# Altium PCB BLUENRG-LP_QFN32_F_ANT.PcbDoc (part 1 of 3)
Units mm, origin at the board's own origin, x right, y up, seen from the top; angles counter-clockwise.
Board outline 90.84 x 54.03 mm, 4 copper layers (Top Layer, G1 Layer, G2 Layer, Bottom Layer), stack 1.697 mm thick; 142 components, 101 nets, 450 pads, 662 vias.
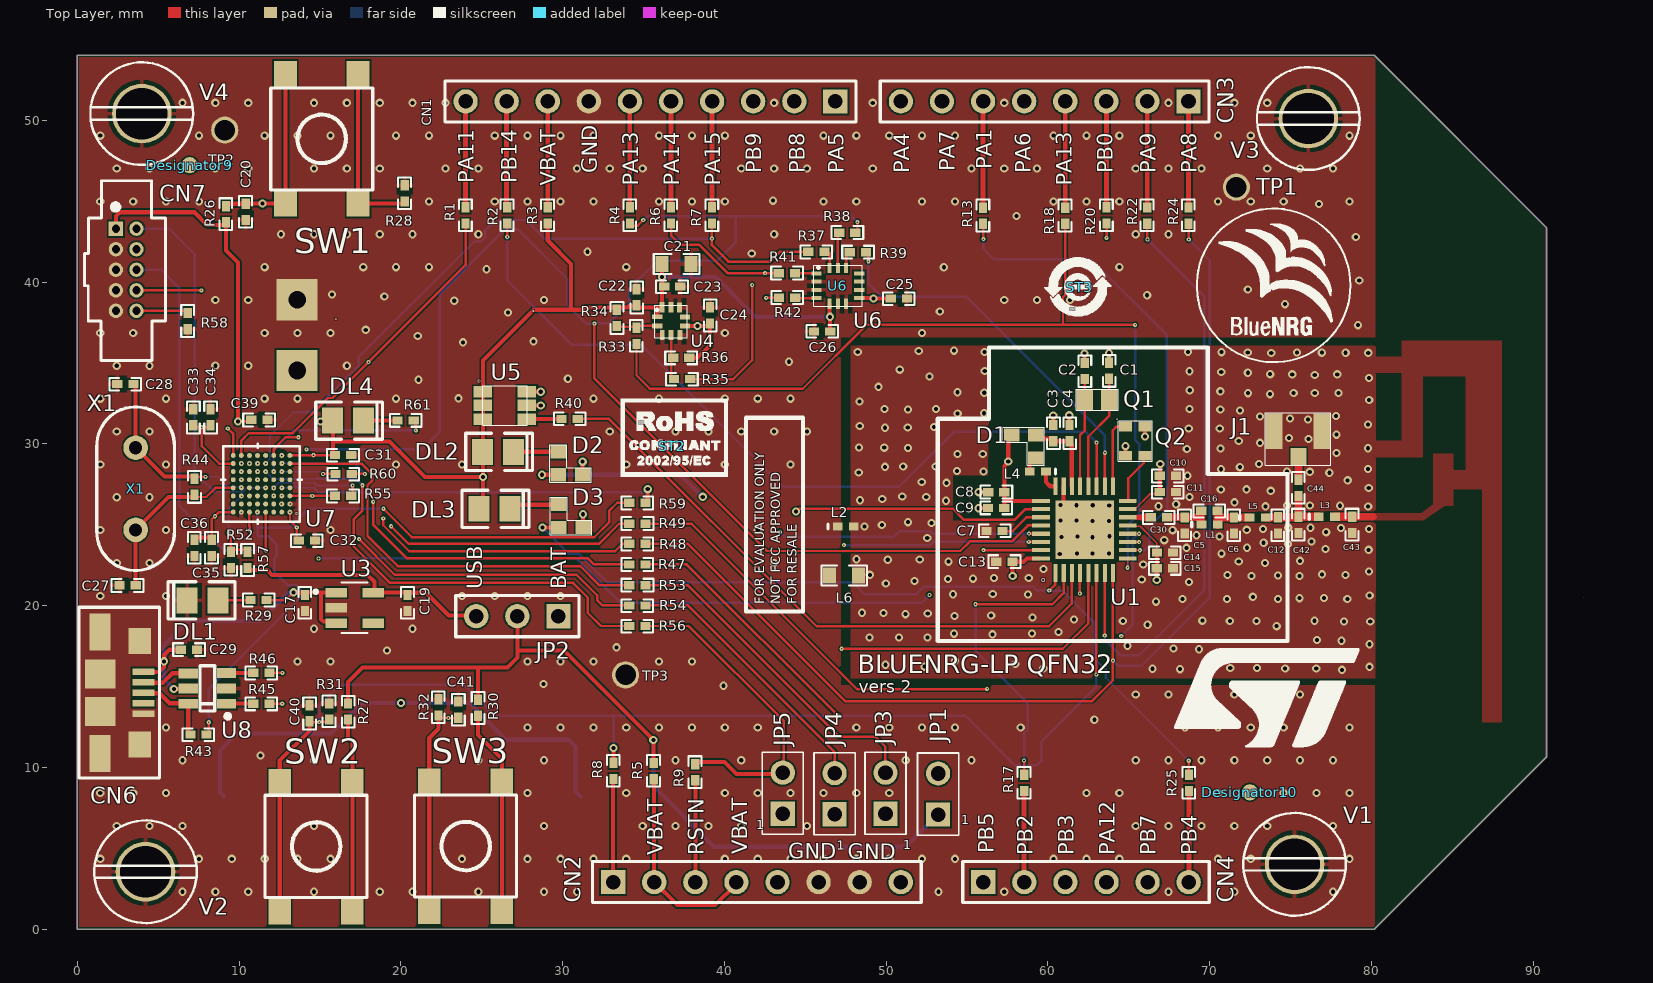
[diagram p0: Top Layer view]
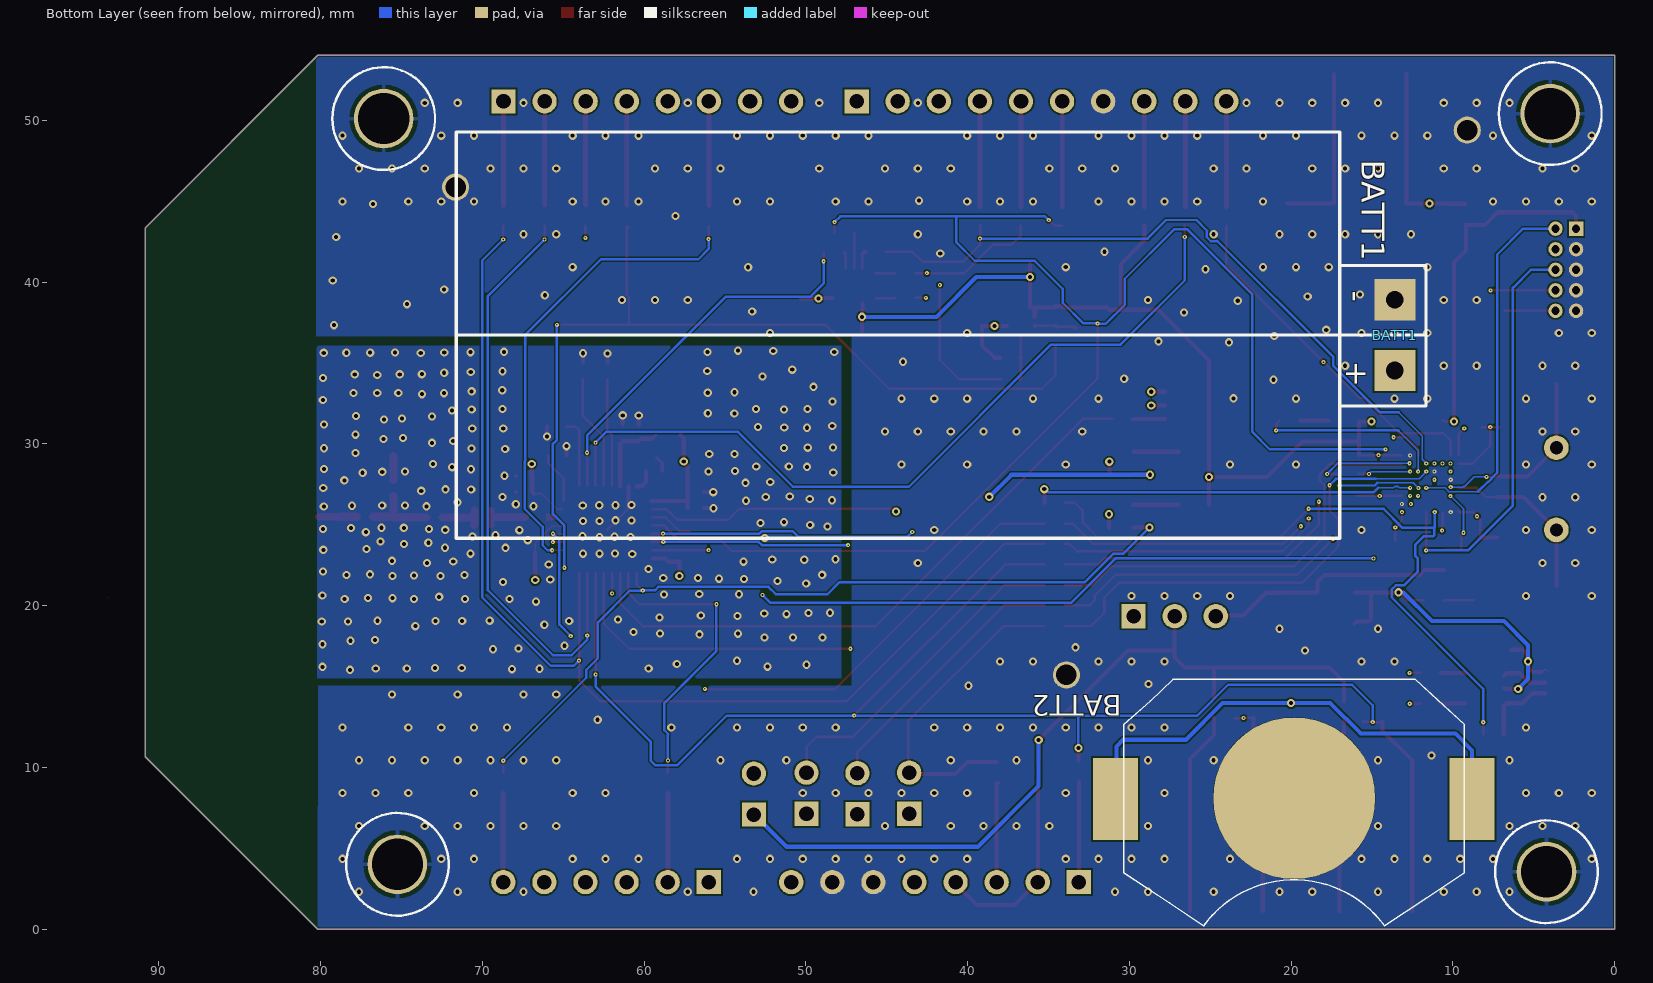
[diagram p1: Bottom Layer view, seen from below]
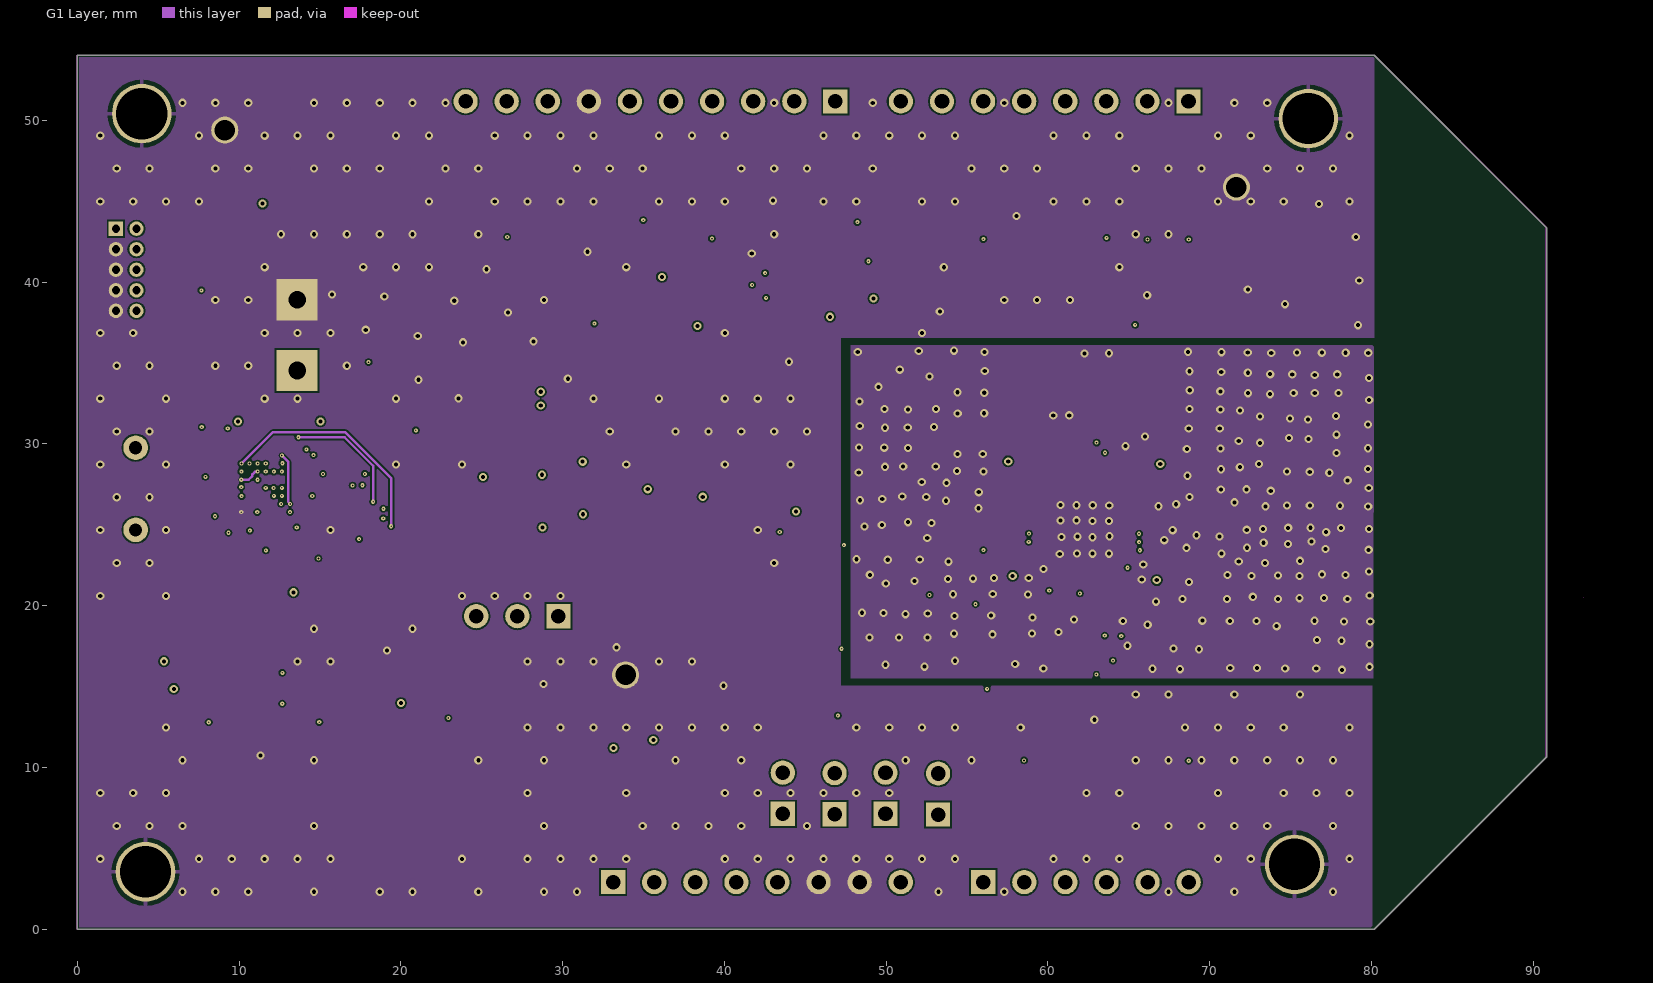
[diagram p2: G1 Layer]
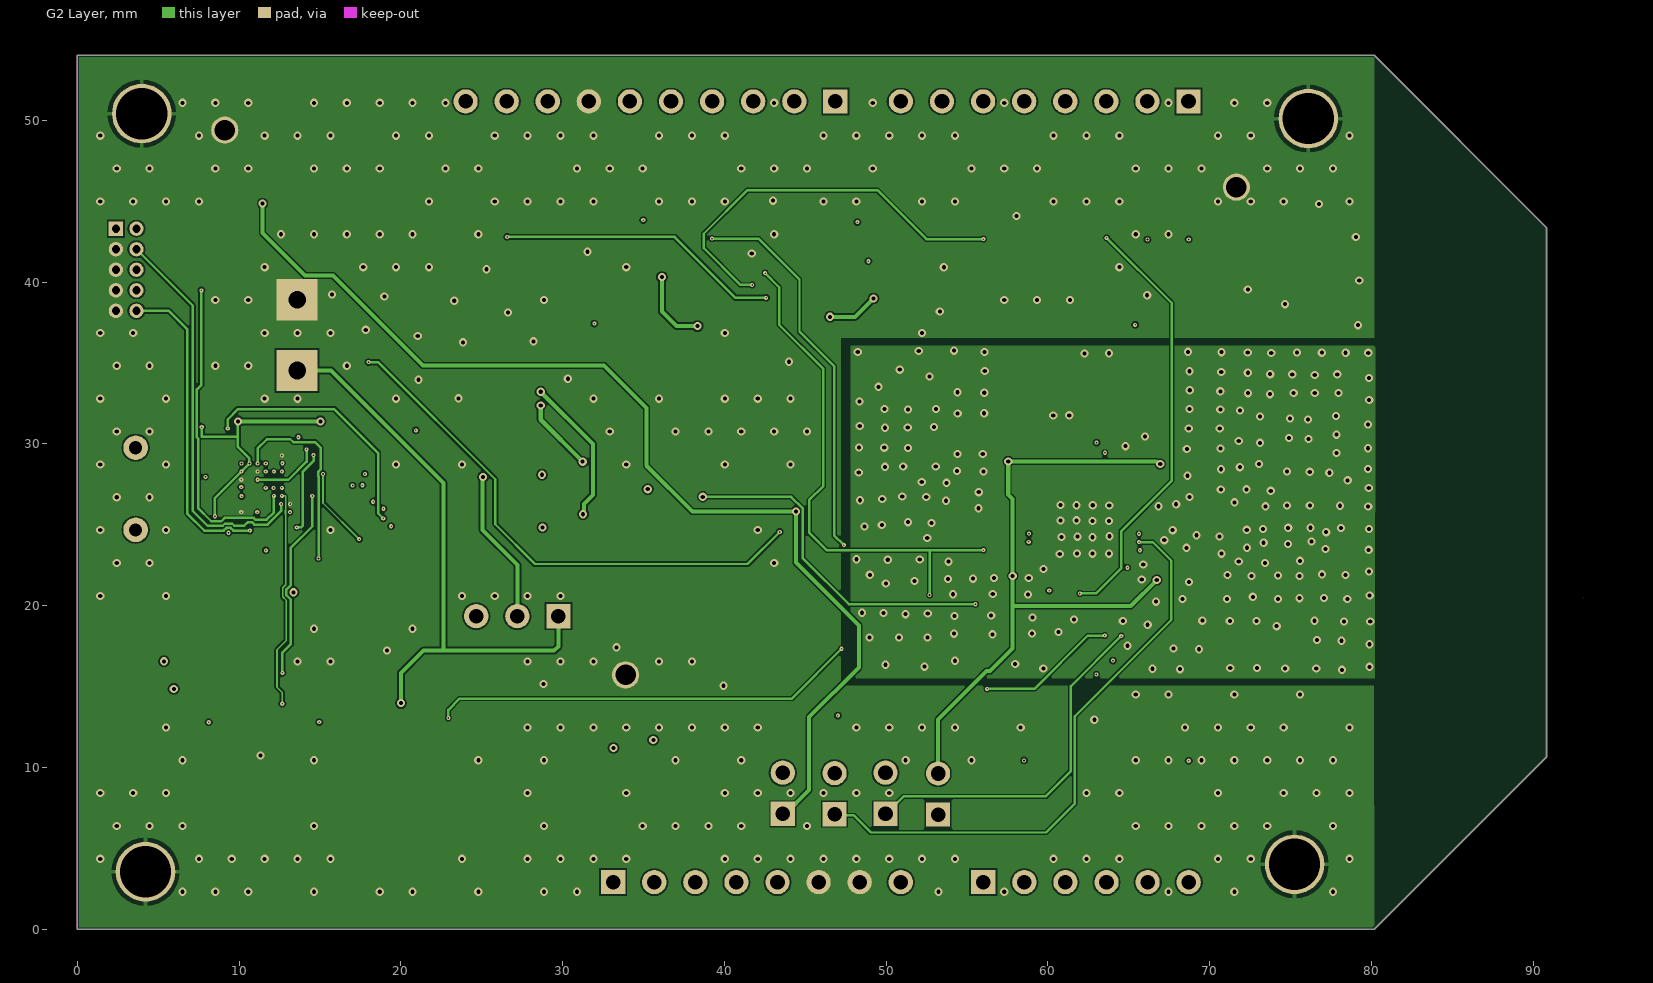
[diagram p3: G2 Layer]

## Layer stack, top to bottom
Top Solder: solder mask 0.0102, Solder Resist, Dk 3.5
Top Layer: signal copper 0.0356
Dielectric 1: dielectric 0.2997, FR-4, Dk 4.3
G1 Layer: signal copper 0.0178
Dielectric2: dielectric 0.9906, FR-4, Dk 4.3
G2 Layer: signal copper 0.0178
Dielectric3: dielectric 0.2997, FR-4, Dk 4.3
Bottom Layer: signal copper 0.0356
Bottom Solder: solder mask 0.0102, Solder Resist, Dk 3.5

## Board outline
0,0 80.169,0 90.838,10.669 90.838,43.357 80.169,54.026 0,54.026
cut-out: 93.094,20.529

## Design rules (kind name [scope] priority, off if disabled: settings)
Clearance Clearance_2 [InNamedPolygon('NONET_TOP_LAYER_P040')] p1: gap=0 ignorepadtopadclearanceinfootprint=FALSE
Clearance Clearance_1 [InNamedPolygon('NONET_TOP_LAYER_P040') vs InNet('GND_RF')] p2: gap=0.254 ignorepadtopadclearanceinfootprint=FALSE except(0: Arc-Hole Track-Hole SMDPad-Hole THPad-Hole Via-Hole Fill-Hole Poly-Hole Region-Hole Text-Hole)
Clearance "Stitching GND_1" [IsStitchingVia and InNet('GND') vs (IsVia and (Not IsStitchingVia)) Or IsPad] p3: gap=0.102 ignorepadtopadclearanceinfootprint=FALSE except(0: SMDPad-Via)
Clearance "Stitching GND" [IsStitchingVia and InNet('GND_RF') vs (IsVia and (Not IsStitchingVia)) Or IsPad] p4: gap=0.102 ignorepadtopadclearanceinfootprint=FALSE
Clearance [All] p5: gap=0.102 ignorepadtopadclearanceinfootprint=FALSE
ComponentClearance [All] p1: gap=0.127 collisioncheckmode=3 verticalgap=0.127 showdistances=FALSE
HoleSize [All] p1: absolutevalues=TRUE maxlimit=5.08 minlimit=0.025 maxpercent=80.000 minpercent=20.000
HoleToHoleClearance [All] p1: gap=0.127 allowstackedmicrovias=TRUE
MinimumSolderMaskSliver [All] p1: minsoldermaskwidth=0
PlaneConnect [All] p1: planeconnectstyle=Relief reliefexpansion=2.54 reliefentries=4 reliefconductorwidth=2.54 reliefairgap=2.54
PolygonConnect [All] p1: connectstyle=Relief reliefconductorwidth=0.254 reliefentries=4 polygonreliefangle="90 Angle" airgapwidth=0.254
RoutingLayers RoutingLayers_1 [All] p1: top layer_v5=TRUE mid layer 1_v5=TRUE mid layer 2_v5=TRUE bottom layer_v5=TRUE
RoutingLayers [All] p2: top layer_v5=TRUE mid layer 1_v5=TRUE mid layer 2_v5=TRUE bottom layer_v5=TRUE
RoutingVias [All] p1: holewidth=0.711 width=1.27 viastyle="Through Hole" minholewidth=0 minwidth=0.254 maxholewidth=0.254 maxwidth=0.508
ShortCircuit [InNamedPolygon('NONET_TOP_LAYER_P040') vs InNamedPolygon('Top Layer-GND_RF')] p1: allowed=TRUE
SilkToSilkClearance [All] p1: silktosilkclearance=0
SilkToSolderMaskClearance [IsPad] p1: minsilkscreentomaskgap=0 clearancetoexposedcopper=TRUE
SolderMaskExpansion [All] p1: expansion=0
ViasUnderSMD VIA_UnderSMD_471 [(Name = 'X1-2')] p1: allowed=TRUE
ViasUnderSMD VIA_UnderSMD_470 [(Name = 'X1-1')] p2: allowed=FALSE
ViasUnderSMD VIA_UnderSMD_469 [(Name = 'V4-1')] p3: allowed=FALSE
ViasUnderSMD VIA_UnderSMD_468 [(Name = 'V3-1')] p4: allowed=FALSE
ViasUnderSMD VIA_UnderSMD_467 [(Name = 'V2-1')] p5: allowed=FALSE
ViasUnderSMD VIA_UnderSMD_466 [(Name = 'V1-1')] p6: allowed=FALSE
ViasUnderSMD VIA_UnderSMD_465 [(Name = 'U9-8')] p7: allowed=FALSE
ViasUnderSMD VIA_UnderSMD_464 [(Name = 'U9-7')] p8: allowed=FALSE
ViasUnderSMD VIA_UnderSMD_463 [(Name = 'U9-6')] p9: allowed=FALSE
ViasUnderSMD VIA_UnderSMD_462 [(Name = 'U9-5')] p10: allowed=FALSE
ViasUnderSMD VIA_UnderSMD_461 [(Name = 'U9-4')] p11: allowed=FALSE
ViasUnderSMD VIA_UnderSMD_460 [(Name = 'U9-3')] p12: allowed=FALSE
ViasUnderSMD VIA_UnderSMD_459 [(Name = 'U9-2')] p13: allowed=FALSE
ViasUnderSMD VIA_UnderSMD_458 [(Name = 'U9-1')] p14: allowed=FALSE
ViasUnderSMD VIA_UnderSMD_457 [(Name = 'U8-6')] p15: allowed=FALSE
ViasUnderSMD VIA_UnderSMD_456 [(Name = 'U8-5')] p16: allowed=FALSE
ViasUnderSMD VIA_UnderSMD_455 [(Name = 'U8-4')] p17: allowed=FALSE
ViasUnderSMD VIA_UnderSMD_454 [(Name = 'U8-3')] p18: allowed=FALSE
ViasUnderSMD VIA_UnderSMD_453 [(Name = 'U8-2')] p19: allowed=FALSE
ViasUnderSMD VIA_UnderSMD_452 [(Name = 'U8-1')] p20: allowed=FALSE
ViasUnderSMD VIA_UnderSMD_451 [(Name = 'U7-48')] p21: allowed=FALSE
ViasUnderSMD VIA_UnderSMD_450 [(Name = 'U7-47')] p22: allowed=FALSE
ViasUnderSMD VIA_UnderSMD_449 [(Name = 'U7-46')] p23: allowed=FALSE
ViasUnderSMD VIA_UnderSMD_448 [(Name = 'U7-45')] p24: allowed=FALSE
ViasUnderSMD VIA_UnderSMD_447 [(Name = 'U7-44')] p25: allowed=FALSE
ViasUnderSMD VIA_UnderSMD_446 [(Name = 'U7-43')] p26: allowed=FALSE
ViasUnderSMD VIA_UnderSMD_445 [(Name = 'U7-42')] p27: allowed=FALSE
ViasUnderSMD VIA_UnderSMD_444 [(Name = 'U7-41')] p28: allowed=FALSE
ViasUnderSMD VIA_UnderSMD_443 [(Name = 'U7-40')] p29: allowed=FALSE
ViasUnderSMD VIA_UnderSMD_442 [(Name = 'U7-39')] p30: allowed=FALSE
ViasUnderSMD VIA_UnderSMD_441 [(Name = 'U7-38')] p31: allowed=FALSE
ViasUnderSMD VIA_UnderSMD_440 [(Name = 'U7-37')] p32: allowed=FALSE
ViasUnderSMD VIA_UnderSMD_439 [(Name = 'U7-36')] p33: allowed=FALSE
ViasUnderSMD VIA_UnderSMD_438 [(Name = 'U7-35')] p34: allowed=FALSE
ViasUnderSMD VIA_UnderSMD_437 [(Name = 'U7-34')] p35: allowed=FALSE
ViasUnderSMD VIA_UnderSMD_436 [(Name = 'U7-33')] p36: allowed=FALSE
ViasUnderSMD VIA_UnderSMD_435 [(Name = 'U7-32')] p37: allowed=FALSE
ViasUnderSMD VIA_UnderSMD_434 [(Name = 'U7-31')] p38: allowed=FALSE
ViasUnderSMD VIA_UnderSMD_433 [(Name = 'U7-30')] p39: allowed=FALSE
ViasUnderSMD VIA_UnderSMD_432 [(Name = 'U7-29')] p40: allowed=FALSE
ViasUnderSMD VIA_UnderSMD_431 [(Name = 'U7-49')] p41: allowed=FALSE
ViasUnderSMD VIA_UnderSMD_430 [(Name = 'U7-28')] p42: allowed=FALSE
ViasUnderSMD VIA_UnderSMD_429 [(Name = 'U7-27')] p43: allowed=FALSE
ViasUnderSMD VIA_UnderSMD_428 [(Name = 'U7-26')] p44: allowed=FALSE
ViasUnderSMD VIA_UnderSMD_427 [(Name = 'U7-25')] p45: allowed=FALSE
ViasUnderSMD VIA_UnderSMD_426 [(Name = 'U7-24')] p46: allowed=FALSE
ViasUnderSMD VIA_UnderSMD_425 [(Name = 'U7-23')] p47: allowed=FALSE
ViasUnderSMD VIA_UnderSMD_424 [(Name = 'U7-22')] p48: allowed=FALSE
ViasUnderSMD VIA_UnderSMD_423 [(Name = 'U7-21')] p49: allowed=FALSE
ViasUnderSMD VIA_UnderSMD_422 [(Name = 'U7-20')] p50: allowed=FALSE
ViasUnderSMD VIA_UnderSMD_421 [(Name = 'U7-19')] p51: allowed=FALSE
ViasUnderSMD VIA_UnderSMD_420 [(Name = 'U7-18')] p52: allowed=FALSE
ViasUnderSMD VIA_UnderSMD_419 [(Name = 'U7-17')] p53: allowed=FALSE
ViasUnderSMD VIA_UnderSMD_418 [(Name = 'U7-16')] p54: allowed=FALSE
ViasUnderSMD VIA_UnderSMD_417 [(Name = 'U7-15')] p55: allowed=FALSE
ViasUnderSMD VIA_UnderSMD_416 [(Name = 'U7-14')] p56: allowed=FALSE
ViasUnderSMD VIA_UnderSMD_415 [(Name = 'U7-13')] p57: allowed=FALSE
ViasUnderSMD VIA_UnderSMD_414 [(Name = 'U7-12')] p58: allowed=FALSE
ViasUnderSMD VIA_UnderSMD_413 [(Name = 'U7-11')] p59: allowed=FALSE
ViasUnderSMD VIA_UnderSMD_412 [(Name = 'U7-10')] p60: allowed=FALSE
ViasUnderSMD VIA_UnderSMD_411 [(Name = 'U7-9')] p61: allowed=FALSE
ViasUnderSMD VIA_UnderSMD_410 [(Name = 'U7-8')] p62: allowed=FALSE
ViasUnderSMD VIA_UnderSMD_409 [(Name = 'U7-7')] p63: allowed=FALSE
ViasUnderSMD VIA_UnderSMD_408 [(Name = 'U7-6')] p64: allowed=FALSE
ViasUnderSMD VIA_UnderSMD_407 [(Name = 'U7-5')] p65: allowed=FALSE
ViasUnderSMD VIA_UnderSMD_406 [(Name = 'U7-4')] p66: allowed=FALSE
ViasUnderSMD VIA_UnderSMD_405 [(Name = 'U7-3')] p67: allowed=FALSE
ViasUnderSMD VIA_UnderSMD_404 [(Name = 'U7-2')] p68: allowed=FALSE
ViasUnderSMD VIA_UnderSMD_403 [(Name = 'U7-1')] p69: allowed=FALSE
ViasUnderSMD VIA_UnderSMD_402 [(Name = 'U6-14')] p70: allowed=FALSE
ViasUnderSMD VIA_UnderSMD_401 [(Name = 'U6-13')] p71: allowed=FALSE
ViasUnderSMD VIA_UnderSMD_400 [(Name = 'U6-12')] p72: allowed=FALSE
ViasUnderSMD VIA_UnderSMD_399 [(Name = 'U6-11')] p73: allowed=FALSE
ViasUnderSMD VIA_UnderSMD_398 [(Name = 'U6-10')] p74: allowed=FALSE
ViasUnderSMD VIA_UnderSMD_397 [(Name = 'U6-9')] p75: allowed=FALSE
ViasUnderSMD VIA_UnderSMD_396 [(Name = 'U6-8')] p76: allowed=FALSE
ViasUnderSMD VIA_UnderSMD_395 [(Name = 'U6-7')] p77: allowed=FALSE
ViasUnderSMD VIA_UnderSMD_394 [(Name = 'U6-6')] p78: allowed=FALSE
ViasUnderSMD VIA_UnderSMD_393 [(Name = 'U6-5')] p79: allowed=FALSE
ViasUnderSMD VIA_UnderSMD_392 [(Name = 'U6-4')] p80: allowed=FALSE
ViasUnderSMD VIA_UnderSMD_391 [(Name = 'U6-3')] p81: allowed=FALSE
ViasUnderSMD VIA_UnderSMD_390 [(Name = 'U6-2')] p82: allowed=FALSE
ViasUnderSMD VIA_UnderSMD_389 [(Name = 'U6-1')] p83: allowed=FALSE
ViasUnderSMD VIA_UnderSMD_388 [(Name = 'U5-6')] p84: allowed=FALSE
ViasUnderSMD VIA_UnderSMD_387 [(Name = 'U5-5')] p85: allowed=FALSE
ViasUnderSMD VIA_UnderSMD_386 [(Name = 'U5-4')] p86: allowed=FALSE
ViasUnderSMD VIA_UnderSMD_385 [(Name = 'U5-3')] p87: allowed=FALSE
ViasUnderSMD VIA_UnderSMD_384 [(Name = 'U5-2')] p88: allowed=FALSE
ViasUnderSMD VIA_UnderSMD_383 [(Name = 'U5-1')] p89: allowed=FALSE
ViasUnderSMD VIA_UnderSMD_382 [(Name = 'U4-10')] p90: allowed=FALSE
ViasUnderSMD VIA_UnderSMD_381 [(Name = 'U4-9')] p91: allowed=FALSE
ViasUnderSMD VIA_UnderSMD_380 [(Name = 'U4-8')] p92: allowed=FALSE
ViasUnderSMD VIA_UnderSMD_379 [(Name = 'U4-7')] p93: allowed=FALSE
ViasUnderSMD VIA_UnderSMD_378 [(Name = 'U4-6')] p94: allowed=FALSE
ViasUnderSMD VIA_UnderSMD_377 [(Name = 'U4-5')] p95: allowed=FALSE
ViasUnderSMD VIA_UnderSMD_376 [(Name = 'U4-4')] p96: allowed=FALSE
ViasUnderSMD VIA_UnderSMD_375 [(Name = 'U4-3')] p97: allowed=FALSE
ViasUnderSMD VIA_UnderSMD_374 [(Name = 'U4-2')] p98: allowed=FALSE
ViasUnderSMD VIA_UnderSMD_373 [(Name = 'U4-1')] p99: allowed=FALSE
ViasUnderSMD VIA_UnderSMD_372 [(Name = 'U3-7')] p100: allowed=FALSE
ViasUnderSMD VIA_UnderSMD_371 [(Name = 'U3-6')] p101: allowed=FALSE
ViasUnderSMD VIA_UnderSMD_370 [(Name = 'U3-5')] p102: allowed=FALSE
ViasUnderSMD VIA_UnderSMD_369 [(Name = 'U3-1')] p103: allowed=FALSE
ViasUnderSMD VIA_UnderSMD_368 [(Name = 'U3-2')] p104: allowed=FALSE
ViasUnderSMD VIA_UnderSMD_367 [(Name = 'U3-3')] p105: allowed=FALSE
ViasUnderSMD VIA_UnderSMD_366 [(Name = 'U3-4')] p106: allowed=FALSE
ViasUnderSMD VIA_UnderSMD_365 [(Name = 'U2-3')] p107: allowed=FALSE
ViasUnderSMD VIA_UnderSMD_364 [(Name = 'U2-1')] p108: allowed=FALSE
ViasUnderSMD VIA_UnderSMD_363 [(Name = 'U2-2')] p109: allowed=FALSE
ViasUnderSMD VIA_UnderSMD_362 [(Name = 'U2-4')] p110: allowed=FALSE
ViasUnderSMD VIA_UnderSMD_361 [(Name = 'U1-48')] p111: allowed=FALSE
ViasUnderSMD VIA_UnderSMD_360 [(Name = 'U1-47')] p112: allowed=FALSE
ViasUnderSMD VIA_UnderSMD_359 [(Name = 'U1-46')] p113: allowed=FALSE
ViasUnderSMD VIA_UnderSMD_358 [(Name = 'U1-45')] p114: allowed=FALSE
ViasUnderSMD VIA_UnderSMD_357 [(Name = 'U1-44')] p115: allowed=FALSE
ViasUnderSMD VIA_UnderSMD_356 [(Name = 'U1-43')] p116: allowed=FALSE
ViasUnderSMD VIA_UnderSMD_355 [(Name = 'U1-42')] p117: allowed=FALSE
ViasUnderSMD VIA_UnderSMD_354 [(Name = 'U1-41')] p118: allowed=FALSE
ViasUnderSMD VIA_UnderSMD_353 [(Name = 'U1-40')] p119: allowed=FALSE
ViasUnderSMD VIA_UnderSMD_352 [(Name = 'U1-39')] p120: allowed=FALSE
ViasUnderSMD VIA_UnderSMD_351 [(Name = 'U1-38')] p121: allowed=FALSE
ViasUnderSMD VIA_UnderSMD_350 [(Name = 'U1-37')] p122: allowed=FALSE
ViasUnderSMD VIA_UnderSMD_349 [(Name = 'U1-36')] p123: allowed=FALSE
ViasUnderSMD VIA_UnderSMD_348 [(Name = 'U1-35')] p124: allowed=FALSE
ViasUnderSMD VIA_UnderSMD_347 [(Name = 'U1-34')] p125: allowed=FALSE
ViasUnderSMD VIA_UnderSMD_346 [(Name = 'U1-33')] p126: allowed=FALSE
ViasUnderSMD VIA_UnderSMD_345 [(Name = 'U1-32')] p127: allowed=FALSE
ViasUnderSMD VIA_UnderSMD_344 [(Name = 'U1-31')] p128: allowed=FALSE
ViasUnderSMD VIA_UnderSMD_343 [(Name = 'U1-30')] p129: allowed=FALSE
ViasUnderSMD VIA_UnderSMD_342 [(Name = 'U1-29')] p130: allowed=FALSE
ViasUnderSMD VIA_UnderSMD_341 [(Name = 'U1-49')] p131: allowed=FALSE
ViasUnderSMD VIA_UnderSMD_340 [(Name = 'U1-28')] p132: allowed=FALSE
ViasUnderSMD VIA_UnderSMD_339 [(Name = 'U1-27')] p133: allowed=FALSE
ViasUnderSMD VIA_UnderSMD_338 [(Name = 'U1-26')] p134: allowed=FALSE
ViasUnderSMD VIA_UnderSMD_337 [(Name = 'U1-25')] p135: allowed=FALSE
ViasUnderSMD VIA_UnderSMD_336 [(Name = 'U1-24')] p136: allowed=FALSE
ViasUnderSMD VIA_UnderSMD_335 [(Name = 'U1-23')] p137: allowed=FALSE
ViasUnderSMD VIA_UnderSMD_334 [(Name = 'U1-22')] p138: allowed=FALSE
ViasUnderSMD VIA_UnderSMD_333 [(Name = 'U1-21')] p139: allowed=FALSE
ViasUnderSMD VIA_UnderSMD_332 [(Name = 'U1-20')] p140: allowed=FALSE
ViasUnderSMD VIA_UnderSMD_331 [(Name = 'U1-19')] p141: allowed=FALSE
ViasUnderSMD VIA_UnderSMD_330 [(Name = 'U1-18')] p142: allowed=FALSE
ViasUnderSMD VIA_UnderSMD_329 [(Name = 'U1-17')] p143: allowed=FALSE
ViasUnderSMD VIA_UnderSMD_328 [(Name = 'U1-16')] p144: allowed=FALSE
ViasUnderSMD VIA_UnderSMD_327 [(Name = 'U1-15')] p145: allowed=FALSE
ViasUnderSMD VIA_UnderSMD_326 [(Name = 'U1-14')] p146: allowed=FALSE
ViasUnderSMD VIA_UnderSMD_325 [(Name = 'U1-13')] p147: allowed=FALSE
ViasUnderSMD VIA_UnderSMD_324 [(Name = 'U1-12')] p148: allowed=FALSE
ViasUnderSMD VIA_UnderSMD_323 [(Name = 'U1-11')] p149: allowed=FALSE
ViasUnderSMD VIA_UnderSMD_322 [(Name = 'U1-10')] p150: allowed=FALSE
ViasUnderSMD VIA_UnderSMD_321 [(Name = 'U1-9')] p151: allowed=FALSE
ViasUnderSMD VIA_UnderSMD_320 [(Name = 'U1-8')] p152: allowed=FALSE
ViasUnderSMD VIA_UnderSMD_319 [(Name = 'U1-7')] p153: allowed=FALSE
ViasUnderSMD VIA_UnderSMD_318 [(Name = 'U1-6')] p154: allowed=FALSE
ViasUnderSMD VIA_UnderSMD_317 [(Name = 'U1-5')] p155: allowed=FALSE
ViasUnderSMD VIA_UnderSMD_316 [(Name = 'U1-4')] p156: allowed=FALSE
ViasUnderSMD VIA_UnderSMD_315 [(Name = 'U1-3')] p157: allowed=FALSE
ViasUnderSMD VIA_UnderSMD_314 [(Name = 'U1-2')] p158: allowed=FALSE
ViasUnderSMD VIA_UnderSMD_313 [(Name = 'U1-1')] p159: allowed=FALSE
ViasUnderSMD VIA_UnderSMD_312 [(Name = 'TP3-1')] p160: allowed=FALSE
ViasUnderSMD VIA_UnderSMD_311 [(Name = 'TP2-1')] p161: allowed=FALSE
ViasUnderSMD VIA_UnderSMD_310 [(Name = 'TP1-1')] p162: allowed=FALSE
ViasUnderSMD VIA_UnderSMD_309 [(Name = 'SW3-4')] p163: allowed=FALSE
ViasUnderSMD VIA_UnderSMD_308 [(Name = 'SW3-3')] p164: allowed=FALSE
ViasUnderSMD VIA_UnderSMD_307 [(Name = 'SW3-2')] p165: allowed=FALSE
ViasUnderSMD VIA_UnderSMD_306 [(Name = 'SW3-1')] p166: allowed=FALSE
ViasUnderSMD VIA_UnderSMD_305 [(Name = 'SW2-4')] p167: allowed=FALSE
ViasUnderSMD VIA_UnderSMD_304 [(Name = 'SW2-3')] p168: allowed=FALSE
ViasUnderSMD VIA_UnderSMD_303 [(Name = 'SW2-2')] p169: allowed=FALSE
ViasUnderSMD VIA_UnderSMD_302 [(Name = 'SW2-1')] p170: allowed=FALSE
ViasUnderSMD VIA_UnderSMD_301 [(Name = 'SW1-4')] p171: allowed=FALSE
ViasUnderSMD VIA_UnderSMD_300 [(Name = 'SW1-3')] p172: allowed=FALSE
ViasUnderSMD VIA_UnderSMD_299 [(Name = 'SW1-2')] p173: allowed=FALSE
ViasUnderSMD VIA_UnderSMD_298 [(Name = 'SW1-1')] p174: allowed=FALSE
ViasUnderSMD VIA_UnderSMD_297 [(Name = 'R61-2')] p175: allowed=FALSE
ViasUnderSMD VIA_UnderSMD_296 [(Name = 'R61-1')] p176: allowed=FALSE
ViasUnderSMD VIA_UnderSMD_295 [(Name = 'R60-2')] p177: allowed=FALSE
ViasUnderSMD VIA_UnderSMD_294 [(Name = 'R60-1')] p178: allowed=FALSE
ViasUnderSMD VIA_UnderSMD_293 [(Name = 'R59-2')] p179: allowed=FALSE
ViasUnderSMD VIA_UnderSMD_292 [(Name = 'R59-1')] p180: allowed=FALSE
ViasUnderSMD VIA_UnderSMD_291 [(Name = 'R58-2')] p181: allowed=FALSE
ViasUnderSMD VIA_UnderSMD_290 [(Name = 'R58-1')] p182: allowed=FALSE
ViasUnderSMD VIA_UnderSMD_289 [(Name = 'R57-2')] p183: allowed=FALSE
ViasUnderSMD VIA_UnderSMD_288 [(Name = 'R57-1')] p184: allowed=FALSE
ViasUnderSMD VIA_UnderSMD_287 [(Name = 'R56-2')] p185: allowed=FALSE
ViasUnderSMD VIA_UnderSMD_286 [(Name = 'R56-1')] p186: allowed=FALSE
ViasUnderSMD VIA_UnderSMD_285 [(Name = 'R55-2')] p187: allowed=FALSE
ViasUnderSMD VIA_UnderSMD_284 [(Name = 'R55-1')] p188: allowed=FALSE
ViasUnderSMD VIA_UnderSMD_283 [(Name = 'R54-2')] p189: allowed=FALSE
ViasUnderSMD VIA_UnderSMD_282 [(Name = 'R54-1')] p190: allowed=FALSE
ViasUnderSMD VIA_UnderSMD_281 [(Name = 'R53-2')] p191: allowed=FALSE
ViasUnderSMD VIA_UnderSMD_280 [(Name = 'R53-1')] p192: allowed=FALSE
ViasUnderSMD VIA_UnderSMD_279 [(Name = 'R52-2')] p193: allowed=FALSE
ViasUnderSMD VIA_UnderSMD_278 [(Name = 'R52-1')] p194: allowed=FALSE
ViasUnderSMD VIA_UnderSMD_277 [(Name = 'R51-2')] p195: allowed=FALSE
ViasUnderSMD VIA_UnderSMD_276 [(Name = 'R51-1')] p196: allowed=FALSE
ViasUnderSMD VIA_UnderSMD_275 [(Name = 'R50-2')] p197: allowed=FALSE
ViasUnderSMD VIA_UnderSMD_274 [(Name = 'R50-1')] p198: allowed=FALSE
ViasUnderSMD VIA_UnderSMD_273 [(Name = 'R49-2')] p199: allowed=FALSE
ViasUnderSMD VIA_UnderSMD_272 [(Name = 'R49-1')] p200: allowed=FALSE
ViasUnderSMD VIA_UnderSMD_271 [(Name = 'R48-2')] p201: allowed=FALSE
ViasUnderSMD VIA_UnderSMD_270 [(Name = 'R48-1')] p202: allowed=FALSE
ViasUnderSMD VIA_UnderSMD_269 [(Name = 'R47-2')] p203: allowed=FALSE
ViasUnderSMD VIA_UnderSMD_268 [(Name = 'R47-1')] p204: allowed=FALSE
ViasUnderSMD VIA_UnderSMD_267 [(Name = 'R46-2')] p205: allowed=FALSE
ViasUnderSMD VIA_UnderSMD_266 [(Name = 'R46-1')] p206: allowed=FALSE
ViasUnderSMD VIA_UnderSMD_265 [(Name = 'R45-2')] p207: allowed=FALSE
ViasUnderSMD VIA_UnderSMD_264 [(Name = 'R45-1')] p208: allowed=FALSE
ViasUnderSMD VIA_UnderSMD_263 [(Name = 'R44-2')] p209: allowed=FALSE
ViasUnderSMD VIA_UnderSMD_262 [(Name = 'R44-1')] p210: allowed=FALSE
ViasUnderSMD VIA_UnderSMD_261 [(Name = 'R43-2')] p211: allowed=FALSE
ViasUnderSMD VIA_UnderSMD_260 [(Name = 'R43-1')] p212: allowed=FALSE
ViasUnderSMD VIA_UnderSMD_259 [(Name = 'R42-2')] p213: allowed=FALSE
ViasUnderSMD VIA_UnderSMD_258 [(Name = 'R42-1')] p214: allowed=FALSE
ViasUnderSMD VIA_UnderSMD_257 [(Name = 'R41-2')] p215: allowed=FALSE
ViasUnderSMD VIA_UnderSMD_256 [(Name = 'R41-1')] p216: allowed=FALSE
ViasUnderSMD VIA_UnderSMD_255 [(Name = 'R40-2')] p217: allowed=FALSE
ViasUnderSMD VIA_UnderSMD_254 [(Name = 'R40-1')] p218: allowed=FALSE
ViasUnderSMD VIA_UnderSMD_253 [(Name = 'R39-2')] p219: allowed=FALSE
ViasUnderSMD VIA_UnderSMD_252 [(Name = 'R39-1')] p220: allowed=FALSE
ViasUnderSMD VIA_UnderSMD_251 [(Name = 'R38-2')] p221: allowed=FALSE
ViasUnderSMD VIA_UnderSMD_250 [(Name = 'R38-1')] p222: allowed=FALSE
ViasUnderSMD VIA_UnderSMD_249 [(Name = 'R37-2')] p223: allowed=FALSE
ViasUnderSMD VIA_UnderSMD_248 [(Name = 'R37-1')] p224: allowed=FALSE
ViasUnderSMD VIA_UnderSMD_247 [(Name = 'R36-2')] p225: allowed=FALSE
ViasUnderSMD VIA_UnderSMD_246 [(Name = 'R36-1')] p226: allowed=FALSE
ViasUnderSMD VIA_UnderSMD_245 [(Name = 'R35-2')] p227: allowed=FALSE
ViasUnderSMD VIA_UnderSMD_244 [(Name = 'R35-1')] p228: allowed=FALSE
ViasUnderSMD VIA_UnderSMD_243 [(Name = 'R34-2')] p229: allowed=FALSE
ViasUnderSMD VIA_UnderSMD_242 [(Name = 'R34-1')] p230: allowed=FALSE
ViasUnderSMD VIA_UnderSMD_241 [(Name = 'R33-2')] p231: allowed=FALSE
ViasUnderSMD VIA_UnderSMD_240 [(Name = 'R33-1')] p232: allowed=FALSE
ViasUnderSMD VIA_UnderSMD_239 [(Name = 'R32-2')] p233: allowed=FALSE
ViasUnderSMD VIA_UnderSMD_238 [(Name = 'R32-1')] p234: allowed=FALSE
ViasUnderSMD VIA_UnderSMD_237 [(Name = 'R31-2')] p235: allowed=FALSE
ViasUnderSMD VIA_UnderSMD_236 [(Name = 'R31-1')] p236: allowed=FALSE
ViasUnderSMD VIA_UnderSMD_235 [(Name = 'R30-2')] p237: allowed=FALSE
ViasUnderSMD VIA_UnderSMD_234 [(Name = 'R30-1')] p238: allowed=FALSE
ViasUnderSMD VIA_UnderSMD_233 [(Name = 'R29-2')] p239: allowed=FALSE
ViasUnderSMD VIA_UnderSMD_232 [(Name = 'R29-1')] p240: allowed=FALSE
ViasUnderSMD VIA_UnderSMD_231 [(Name = 'R28-2')] p241: allowed=FALSE
ViasUnderSMD VIA_UnderSMD_230 [(Name = 'R28-1')] p242: allowed=FALSE
ViasUnderSMD VIA_UnderSMD_229 [(Name = 'R27-2')] p243: allowed=FALSE
ViasUnderSMD VIA_UnderSMD_228 [(Name = 'R27-1')] p244: allowed=FALSE
ViasUnderSMD VIA_UnderSMD_227 [(Name = 'R26-2')] p245: allowed=FALSE
ViasUnderSMD VIA_UnderSMD_226 [(Name = 'R26-1')] p246: allowed=FALSE
ViasUnderSMD VIA_UnderSMD_225 [(Name = 'R25-2')] p247: allowed=FALSE
ViasUnderSMD VIA_UnderSMD_224 [(Name = 'R25-1')] p248: allowed=FALSE
ViasUnderSMD VIA_UnderSMD_223 [(Name = 'R24-2')] p249: allowed=FALSE
ViasUnderSMD VIA_UnderSMD_222 [(Name = 'R24-1')] p250: allowed=FALSE
ViasUnderSMD VIA_UnderSMD_221 [(Name = 'R23-2')] p251: allowed=FALSE
ViasUnderSMD VIA_UnderSMD_220 [(Name = 'R23-1')] p252: allowed=FALSE
ViasUnderSMD VIA_UnderSMD_219 [(Name = 'R22-2')] p253: allowed=FALSE
ViasUnderSMD VIA_UnderSMD_218 [(Name = 'R22-1')] p254: allowed=FALSE
ViasUnderSMD VIA_UnderSMD_217 [(Name = 'R21-2')] p255: allowed=FALSE
ViasUnderSMD VIA_UnderSMD_216 [(Name = 'R21-1')] p256: allowed=FALSE
ViasUnderSMD VIA_UnderSMD_215 [(Name = 'R20-2')] p257: allowed=FALSE
ViasUnderSMD VIA_UnderSMD_214 [(Name = 'R20-1')] p258: allowed=FALSE
ViasUnderSMD VIA_UnderSMD_213 [(Name = 'R19-2')] p259: allowed=FALSE
ViasUnderSMD VIA_UnderSMD_212 [(Name = 'R19-1')] p260: allowed=FALSE
ViasUnderSMD VIA_UnderSMD_211 [(Name = 'R18-2')] p261: allowed=FALSE
ViasUnderSMD VIA_UnderSMD_210 [(Name = 'R18-1')] p262: allowed=FALSE
ViasUnderSMD VIA_UnderSMD_209 [(Name = 'R17-2')] p263: allowed=FALSE
ViasUnderSMD VIA_UnderSMD_208 [(Name = 'R17-1')] p264: allowed=FALSE
ViasUnderSMD VIA_UnderSMD_207 [(Name = 'R16-2')] p265: allowed=FALSE
ViasUnderSMD VIA_UnderSMD_206 [(Name = 'R16-1')] p266: allowed=FALSE
ViasUnderSMD VIA_UnderSMD_205 [(Name = 'R15-2')] p267: allowed=FALSE
ViasUnderSMD VIA_UnderSMD_204 [(Name = 'R15-1')] p268: allowed=FALSE
ViasUnderSMD VIA_UnderSMD_203 [(Name = 'R14-2')] p269: allowed=FALSE
ViasUnderSMD VIA_UnderSMD_202 [(Name = 'R14-1')] p270: allowed=FALSE
ViasUnderSMD VIA_UnderSMD_201 [(Name = 'R13-2')] p271: allowed=FALSE
ViasUnderSMD VIA_UnderSMD_200 [(Name = 'R13-1')] p272: allowed=FALSE
ViasUnderSMD VIA_UnderSMD_199 [(Name = 'R12-2')] p273: allowed=FALSE
ViasUnderSMD VIA_UnderSMD_198 [(Name = 'R12-1')] p274: allowed=FALSE
ViasUnderSMD VIA_UnderSMD_197 [(Name = 'R11-2')] p275: allowed=FALSE
ViasUnderSMD VIA_UnderSMD_196 [(Name = 'R11-1')] p276: allowed=FALSE
ViasUnderSMD VIA_UnderSMD_195 [(Name = 'R10-2')] p277: allowed=FALSE
ViasUnderSMD VIA_UnderSMD_194 [(Name = 'R10-1')] p278: allowed=FALSE
ViasUnderSMD VIA_UnderSMD_193 [(Name = 'R9-2')] p279: allowed=FALSE
ViasUnderSMD VIA_UnderSMD_192 [(Name = 'R9-1')] p280: allowed=FALSE
ViasUnderSMD VIA_UnderSMD_191 [(Name = 'R8-2')] p281: allowed=FALSE
ViasUnderSMD VIA_UnderSMD_190 [(Name = 'R8-1')] p282: allowed=FALSE
ViasUnderSMD VIA_UnderSMD_189 [(Name = 'R7-2')] p283: allowed=FALSE
ViasUnderSMD VIA_UnderSMD_188 [(Name = 'R7-1')] p284: allowed=FALSE
ViasUnderSMD VIA_UnderSMD_187 [(Name = 'R6-2')] p285: allowed=FALSE
ViasUnderSMD VIA_UnderSMD_186 [(Name = 'R6-1')] p286: allowed=FALSE
ViasUnderSMD VIA_UnderSMD_185 [(Name = 'R5-2')] p287: allowed=FALSE
ViasUnderSMD VIA_UnderSMD_184 [(Name = 'R5-1')] p288: allowed=FALSE
ViasUnderSMD VIA_UnderSMD_183 [(Name = 'R4-2')] p289: allowed=FALSE
ViasUnderSMD VIA_UnderSMD_182 [(Name = 'R4-1')] p290: allowed=FALSE
ViasUnderSMD VIA_UnderSMD_181 [(Name = 'R3-2')] p291: allowed=FALSE
ViasUnderSMD VIA_UnderSMD_180 [(Name = 'R3-1')] p292: allowed=FALSE
ViasUnderSMD VIA_UnderSMD_179 [(Name = 'R2-2')] p293: allowed=FALSE
ViasUnderSMD VIA_UnderSMD_178 [(Name = 'R2-1')] p294: allowed=FALSE
ViasUnderSMD VIA_UnderSMD_177 [(Name = 'R1-2')] p295: allowed=FALSE
ViasUnderSMD VIA_UnderSMD_176 [(Name = 'R1-1')] p296: allowed=FALSE
ViasUnderSMD VIA_UnderSMD_175 [(Name = 'Q2-4')] p297: allowed=FALSE
ViasUnderSMD VIA_UnderSMD_174 [(Name = 'Q2-3')] p298: allowed=FALSE
ViasUnderSMD VIA_UnderSMD_173 [(Name = 'Q2-2')] p299: allowed=FALSE
ViasUnderSMD VIA_UnderSMD_172 [(Name = 'Q2-1')] p300: allowed=FALSE
ViasUnderSMD VIA_UnderSMD_171 [(Name = 'Q1-2')] p301: allowed=FALSE
ViasUnderSMD VIA_UnderSMD_170 [(Name = 'Q1-1')] p302: allowed=FALSE
ViasUnderSMD VIA_UnderSMD_169 [(Name = 'L1-2')] p303: allowed=FALSE
ViasUnderSMD VIA_UnderSMD_168 [(Name = 'L1-1')] p304: allowed=FALSE
ViasUnderSMD VIA_UnderSMD_167 [(Name = 'JP5-2')] p305: allowed=FALSE
ViasUnderSMD VIA_UnderSMD_166 [(Name = 'JP5-1')] p306: allowed=FALSE
ViasUnderSMD VIA_UnderSMD_165 [(Name = 'JP4-2')] p307: allowed=FALSE
ViasUnderSMD VIA_UnderSMD_164 [(Name = 'JP4-1')] p308: allowed=FALSE
ViasUnderSMD VIA_UnderSMD_163 [(Name = 'JP3-2')] p309: allowed=FALSE
ViasUnderSMD VIA_UnderSMD_162 [(Name = 'JP3-1')] p310: allowed=FALSE
ViasUnderSMD VIA_UnderSMD_161 [(Name = 'JP2-3')] p311: allowed=FALSE
ViasUnderSMD VIA_UnderSMD_160 [(Name = 'JP2-2')] p312: allowed=FALSE
ViasUnderSMD VIA_UnderSMD_159 [(Name = 'JP2-1')] p313: allowed=FALSE
ViasUnderSMD VIA_UnderSMD_158 [(Name = 'JP1-2')] p314: allowed=FALSE
ViasUnderSMD VIA_UnderSMD_157 [(Name = 'JP1-1')] p315: allowed=FALSE
ViasUnderSMD VIA_UnderSMD_156 [(Name = 'J1-5')] p316: allowed=FALSE
ViasUnderSMD VIA_UnderSMD_155 [(Name = 'J1-4')] p317: allowed=FALSE
ViasUnderSMD VIA_UnderSMD_154 [(Name = 'J1-3')] p318: allowed=FALSE
ViasUnderSMD VIA_UnderSMD_153 [(Name = 'J1-2')] p319: allowed=FALSE
ViasUnderSMD VIA_UnderSMD_152 [(Name = 'J1-1')] p320: allowed=FALSE
ViasUnderSMD VIA_UnderSMD_151 [(Name = 'DL4-2')] p321: allowed=FALSE
ViasUnderSMD VIA_UnderSMD_150 [(Name = 'DL4-1')] p322: allowed=FALSE
ViasUnderSMD VIA_UnderSMD_149 [(Name = 'DL3-2')] p323: allowed=FALSE
ViasUnderSMD VIA_UnderSMD_148 [(Name = 'DL3-1')] p324: allowed=FALSE
ViasUnderSMD VIA_UnderSMD_147 [(Name = 'DL2-2')] p325: allowed=FALSE
ViasUnderSMD VIA_UnderSMD_146 [(Name = 'DL2-1')] p326: allowed=FALSE
ViasUnderSMD VIA_UnderSMD_145 [(Name = 'DL1-2')] p327: allowed=FALSE
ViasUnderSMD VIA_UnderSMD_144 [(Name = 'DL1-1')] p328: allowed=FALSE
ViasUnderSMD VIA_UnderSMD_143 [(Name = 'D3-3')] p329: allowed=FALSE
ViasUnderSMD VIA_UnderSMD_142 [(Name = 'D3-1')] p330: allowed=FALSE
ViasUnderSMD VIA_UnderSMD_141 [(Name = 'D3-2')] p331: allowed=FALSE
ViasUnderSMD VIA_UnderSMD_140 [(Name = 'D2-3')] p332: allowed=FALSE
ViasUnderSMD VIA_UnderSMD_139 [(Name = 'D2-1')] p333: allowed=FALSE
ViasUnderSMD VIA_UnderSMD_138 [(Name = 'D2-2')] p334: allowed=FALSE
ViasUnderSMD VIA_UnderSMD_137 [(Name = 'D1-3')] p335: allowed=FALSE
ViasUnderSMD VIA_UnderSMD_136 [(Name = 'D1-1')] p336: allowed=FALSE
ViasUnderSMD VIA_UnderSMD_135 [(Name = 'D1-2')] p337: allowed=FALSE
ViasUnderSMD VIA_UnderSMD_134 [(Name = 'CN7-10')] p338: allowed=FALSE
ViasUnderSMD VIA_UnderSMD_133 [(Name = 'CN7-9')] p339: allowed=FALSE
ViasUnderSMD VIA_UnderSMD_132 [(Name = 'CN7-8')] p340: allowed=FALSE
ViasUnderSMD VIA_UnderSMD_131 [(Name = 'CN7-7')] p341: allowed=FALSE
ViasUnderSMD VIA_UnderSMD_130 [(Name = 'CN7-6')] p342: allowed=FALSE
ViasUnderSMD VIA_UnderSMD_129 [(Name = 'CN7-5')] p343: allowed=FALSE
ViasUnderSMD VIA_UnderSMD_128 [(Name = 'CN7-4')] p344: allowed=FALSE
ViasUnderSMD VIA_UnderSMD_127 [(Name = 'CN7-3')] p345: allowed=FALSE
ViasUnderSMD VIA_UnderSMD_126 [(Name = 'CN7-2')] p346: allowed=FALSE
ViasUnderSMD VIA_UnderSMD_125 [(Name = 'CN7-1')] p347: allowed=FALSE
ViasUnderSMD VIA_UnderSMD_124 [(Name = 'CN6-11')] p348: allowed=FALSE
ViasUnderSMD VIA_UnderSMD_123 [(Name = 'CN6-10')] p349: allowed=FALSE
ViasUnderSMD VIA_UnderSMD_122 [(Name = 'CN6-5')] p350: allowed=FALSE
ViasUnderSMD VIA_UnderSMD_121 [(Name = 'CN6-4')] p351: allowed=FALSE
ViasUnderSMD VIA_UnderSMD_120 [(Name = 'CN6-3')] p352: allowed=FALSE
ViasUnderSMD VIA_UnderSMD_119 [(Name = 'CN6-2')] p353: allowed=FALSE
ViasUnderSMD VIA_UnderSMD_118 [(Name = 'CN6-1')] p354: allowed=FALSE
ViasUnderSMD VIA_UnderSMD_117 [(Name = 'CN6-7')] p355: allowed=FALSE
ViasUnderSMD VIA_UnderSMD_116 [(Name = 'CN6-8')] p356: allowed=FALSE
ViasUnderSMD VIA_UnderSMD_115 [(Name = 'CN6-6')] p357: allowed=FALSE
ViasUnderSMD VIA_UnderSMD_114 [(Name = 'CN6-9')] p358: allowed=FALSE
ViasUnderSMD VIA_UnderSMD_113 [(Name = 'CN4-6')] p359: allowed=FALSE
ViasUnderSMD VIA_UnderSMD_112 [(Name = 'CN4-5')] p360: allowed=FALSE
ViasUnderSMD VIA_UnderSMD_111 [(Name = 'CN4-4')] p361: allowed=FALSE
ViasUnderSMD VIA_UnderSMD_110 [(Name = 'CN4-3')] p362: allowed=FALSE
ViasUnderSMD VIA_UnderSMD_109 [(Name = 'CN4-2')] p363: allowed=FALSE
ViasUnderSMD VIA_UnderSMD_108 [(Name = 'CN4-1')] p364: allowed=FALSE
ViasUnderSMD VIA_UnderSMD_107 [(Name = 'CN3-8')] p365: allowed=FALSE
ViasUnderSMD VIA_UnderSMD_106 [(Name = 'CN3-7')] p366: allowed=FALSE
ViasUnderSMD VIA_UnderSMD_105 [(Name = 'CN3-6')] p367: allowed=FALSE
ViasUnderSMD VIA_UnderSMD_104 [(Name = 'CN3-5')] p368: allowed=FALSE
ViasUnderSMD VIA_UnderSMD_103 [(Name = 'CN3-4')] p369: allowed=FALSE
ViasUnderSMD VIA_UnderSMD_102 [(Name = 'CN3-3')] p370: allowed=FALSE
ViasUnderSMD VIA_UnderSMD_101 [(Name = 'CN3-2')] p371: allowed=FALSE
ViasUnderSMD VIA_UnderSMD_100 [(Name = 'CN3-1')] p372: allowed=FALSE
ViasUnderSMD VIA_UnderSMD_99 [(Name = 'CN2-8')] p373: allowed=FALSE
ViasUnderSMD VIA_UnderSMD_98 [(Name = 'CN2-7')] p374: allowed=FALSE
ViasUnderSMD VIA_UnderSMD_97 [(Name = 'CN2-6')] p375: allowed=FALSE
ViasUnderSMD VIA_UnderSMD_96 [(Name = 'CN2-5')] p376: allowed=FALSE
ViasUnderSMD VIA_UnderSMD_95 [(Name = 'CN2-4')] p377: allowed=FALSE
ViasUnderSMD VIA_UnderSMD_94 [(Name = 'CN2-3')] p378: allowed=FALSE
ViasUnderSMD VIA_UnderSMD_93 [(Name = 'CN2-2')] p379: allowed=FALSE
ViasUnderSMD VIA_UnderSMD_92 [(Name = 'CN2-1')] p380: allowed=FALSE
ViasUnderSMD VIA_UnderSMD_91 [(Name = 'CN1-10')] p381: allowed=FALSE
ViasUnderSMD VIA_UnderSMD_90 [(Name = 'CN1-9')] p382: allowed=FALSE
ViasUnderSMD VIA_UnderSMD_89 [(Name = 'CN1-8')] p383: allowed=FALSE
ViasUnderSMD VIA_UnderSMD_88 [(Name = 'CN1-7')] p384: allowed=FALSE
ViasUnderSMD VIA_UnderSMD_87 [(Name = 'CN1-6')] p385: allowed=FALSE
ViasUnderSMD VIA_UnderSMD_86 [(Name = 'CN1-5')] p386: allowed=FALSE
ViasUnderSMD VIA_UnderSMD_85 [(Name = 'CN1-4')] p387: allowed=FALSE
ViasUnderSMD VIA_UnderSMD_84 [(Name = 'CN1-3')] p388: allowed=FALSE
ViasUnderSMD VIA_UnderSMD_83 [(Name = 'CN1-2')] p389: allowed=FALSE
ViasUnderSMD VIA_UnderSMD_82 [(Name = 'CN1-1')] p390: allowed=FALSE
ViasUnderSMD VIA_UnderSMD_81 [(Name = 'C38-2')] p391: allowed=FALSE
ViasUnderSMD VIA_UnderSMD_80 [(Name = 'C38-1')] p392: allowed=FALSE
ViasUnderSMD VIA_UnderSMD_79 [(Name = 'C37-2')] p393: allowed=FALSE
ViasUnderSMD VIA_UnderSMD_78 [(Name = 'C37-1')] p394: allowed=FALSE
ViasUnderSMD VIA_UnderSMD_77 [(Name = 'C36-2')] p395: allowed=FALSE
ViasUnderSMD VIA_UnderSMD_76 [(Name = 'C36-1')] p396: allowed=FALSE
ViasUnderSMD VIA_UnderSMD_75 [(Name = 'C35-2')] p397: allowed=FALSE
ViasUnderSMD VIA_UnderSMD_74 [(Name = 'C35-1')] p398: allowed=FALSE
ViasUnderSMD VIA_UnderSMD_73 [(Name = 'C34-2')] p399: allowed=FALSE
ViasUnderSMD VIA_UnderSMD_72 [(Name = 'C34-1')] p400: allowed=FALSE
ViasUnderSMD VIA_UnderSMD_71 [(Name = 'C33-2')] p401: allowed=FALSE
ViasUnderSMD VIA_UnderSMD_70 [(Name = 'C33-1')] p402: allowed=FALSE
ViasUnderSMD VIA_UnderSMD_69 [(Name = 'C32-2')] p403: allowed=FALSE
ViasUnderSMD VIA_UnderSMD_68 [(Name = 'C32-1')] p404: allowed=FALSE
ViasUnderSMD VIA_UnderSMD_67 [(Name = 'C31-2')] p405: allowed=FALSE
ViasUnderSMD VIA_UnderSMD_66 [(Name = 'C31-1')] p406: allowed=FALSE
ViasUnderSMD VIA_UnderSMD_65 [(Name = 'C30-2')] p407: allowed=FALSE
ViasUnderSMD VIA_UnderSMD_64 [(Name = 'C30-1')] p408: allowed=FALSE
ViasUnderSMD VIA_UnderSMD_63 [(Name = 'C29-2')] p409: allowed=FALSE
ViasUnderSMD VIA_UnderSMD_62 [(Name = 'C29-1')] p410: allowed=FALSE
ViasUnderSMD VIA_UnderSMD_61 [(Name = 'C28-2')] p411: allowed=FALSE
ViasUnderSMD VIA_UnderSMD_60 [(Name = 'C28-1')] p412: allowed=FALSE
ViasUnderSMD VIA_UnderSMD_59 [(Name = 'C27-2')] p413: allowed=FALSE
ViasUnderSMD VIA_UnderSMD_58 [(Name = 'C27-1')] p414: allowed=FALSE
ViasUnderSMD VIA_UnderSMD_57 [(Name = 'C26-2')] p415: allowed=FALSE
ViasUnderSMD VIA_UnderSMD_56 [(Name = 'C26-1')] p416: allowed=FALSE
ViasUnderSMD VIA_UnderSMD_55 [(Name = 'C25-2')] p417: allowed=FALSE
ViasUnderSMD VIA_UnderSMD_54 [(Name = 'C25-1')] p418: allowed=FALSE
ViasUnderSMD VIA_UnderSMD_53 [(Name = 'C24-2')] p419: allowed=FALSE
ViasUnderSMD VIA_UnderSMD_52 [(Name = 'C24-1')] p420: allowed=FALSE
ViasUnderSMD VIA_UnderSMD_51 [(Name = 'C23-2')] p421: allowed=FALSE
ViasUnderSMD VIA_UnderSMD_50 [(Name = 'C23-1')] p422: allowed=FALSE
ViasUnderSMD VIA_UnderSMD_49 [(Name = 'C22-2')] p423: allowed=FALSE
ViasUnderSMD VIA_UnderSMD_48 [(Name = 'C22-1')] p424: allowed=FALSE
ViasUnderSMD VIA_UnderSMD_47 [(Name = 'C21-2')] p425: allowed=FALSE
ViasUnderSMD VIA_UnderSMD_46 [(Name = 'C21-1')] p426: allowed=FALSE
ViasUnderSMD VIA_UnderSMD_45 [(Name = 'C20-2')] p427: allowed=FALSE
ViasUnderSMD VIA_UnderSMD_44 [(Name = 'C20-1')] p428: allowed=FALSE
ViasUnderSMD VIA_UnderSMD_43 [(Name = 'C19-2')] p429: allowed=FALSE
ViasUnderSMD VIA_UnderSMD_42 [(Name = 'C19-1')] p430: allowed=FALSE
ViasUnderSMD VIA_UnderSMD_41 [(Name = 'C18-2')] p431: allowed=FALSE
ViasUnderSMD VIA_UnderSMD_40 [(Name = 'C18-1')] p432: allowed=FALSE
ViasUnderSMD VIA_UnderSMD_39 [(Name = 'C17-2')] p433: allowed=FALSE
ViasUnderSMD VIA_UnderSMD_38 [(Name = 'C17-1')] p434: allowed=FALSE
ViasUnderSMD VIA_UnderSMD_37 [(Name = 'C16-2')] p435: allowed=FALSE
ViasUnderSMD VIA_UnderSMD_36 [(Name = 'C16-1')] p436: allowed=FALSE
ViasUnderSMD VIA_UnderSMD_35 [(Name = 'C15-2')] p437: allowed=FALSE
ViasUnderSMD VIA_UnderSMD_34 [(Name = 'C15-1')] p438: allowed=FALSE
ViasUnderSMD VIA_UnderSMD_33 [(Name = 'C14-2')] p439: allowed=FALSE
ViasUnderSMD VIA_UnderSMD_32 [(Name = 'C14-1')] p440: allowed=FALSE
ViasUnderSMD VIA_UnderSMD_31 [(Name = 'C13-2')] p441: allowed=FALSE
ViasUnderSMD VIA_UnderSMD_30 [(Name = 'C13-1')] p442: allowed=FALSE
ViasUnderSMD VIA_UnderSMD_29 [(Name = 'C12-2')] p443: allowed=FALSE
ViasUnderSMD VIA_UnderSMD_28 [(Name = 'C12-1')] p444: allowed=FALSE
ViasUnderSMD VIA_UnderSMD_27 [(Name = 'C11-2')] p445: allowed=FALSE
ViasUnderSMD VIA_UnderSMD_26 [(Name = 'C11-1')] p446: allowed=FALSE
ViasUnderSMD VIA_UnderSMD_25 [(Name = 'C10-2')] p447: allowed=FALSE
ViasUnderSMD VIA_UnderSMD_24 [(Name = 'C10-1')] p448: allowed=FALSE
ViasUnderSMD VIA_UnderSMD_23 [(Name = 'C9-2')] p449: allowed=FALSE
ViasUnderSMD VIA_UnderSMD_22 [(Name = 'C9-1')] p450: allowed=FALSE
ViasUnderSMD VIA_UnderSMD_21 [(Name = 'C8-2')] p451: allowed=FALSE
ViasUnderSMD VIA_UnderSMD_20 [(Name = 'C8-1')] p452: allowed=FALSE
ViasUnderSMD VIA_UnderSMD_19 [(Name = 'C7-2')] p453: allowed=FALSE
ViasUnderSMD VIA_UnderSMD_18 [(Name = 'C7-1')] p454: allowed=FALSE
ViasUnderSMD VIA_UnderSMD_17 [(Name = 'C6-2')] p455: allowed=FALSE
ViasUnderSMD VIA_UnderSMD_16 [(Name = 'C6-1')] p456: allowed=FALSE
ViasUnderSMD VIA_UnderSMD_15 [(Name = 'C5-2')] p457: allowed=FALSE
ViasUnderSMD VIA_UnderSMD_14 [(Name = 'C5-1')] p458: allowed=FALSE
ViasUnderSMD VIA_UnderSMD_13 [(Name = 'C4-2')] p459: allowed=FALSE
ViasUnderSMD VIA_UnderSMD_12 [(Name = 'C4-1')] p460: allowed=FALSE
ViasUnderSMD VIA_UnderSMD_11 [(Name = 'C3-2')] p461: allowed=FALSE
ViasUnderSMD VIA_UnderSMD_10 [(Name = 'C3-1')] p462: allowed=FALSE
ViasUnderSMD VIA_UnderSMD_9 [(Name = 'C2-2')] p463: allowed=FALSE
ViasUnderSMD VIA_UnderSMD_8 [(Name = 'C2-1')] p464: allowed=FALSE
ViasUnderSMD VIA_UnderSMD_7 [(Name = 'C1-2')] p465: allowed=FALSE
ViasUnderSMD VIA_UnderSMD_6 [(Name = 'C1-1')] p466: allowed=FALSE
ViasUnderSMD VIA_UnderSMD_5 [(Name = 'BATT2-3')] p467: allowed=FALSE
ViasUnderSMD VIA_UnderSMD_4 [(Name = 'BATT2-2')] p468: allowed=FALSE
ViasUnderSMD VIA_UnderSMD_3 [(Name = 'BATT2-1')] p469: allowed=FALSE
ViasUnderSMD VIA_UnderSMD_2 [(Name = 'BATT1-1')] p470: allowed=FALSE
ViasUnderSMD VIA_UnderSMD_1 [(Name = 'BATT1-2')] p471: allowed=FALSE
Width [All] p1: maxlimit=0.762 minlimit=0.102 preferedwidth=0.152
21 further rules are at their usual default settings.

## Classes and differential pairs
component class USB_MICRO: C27 C28 C29 C31 C32 C33 C34 C35 C36 C39 CN6 CN7 DL4 R43 R44 R45 R46 R47 R48 R49 R52 R53 R54 R55 R56 R57 R58 R59 R60 R61 ST1 ST2 ST3 TP1 TP2 TP3 U7 U8 V1 V2 V3 V4 X1
component class Supply: BATT1 BATT2 C17 C19 C20 C21 C22 C23 C24 C25 C26 C40 C41 D2 D3 DL1 DL2 DL3 JP2 R26 R27 R28 R29 R30 R31 R32 R33 R34 R35 R36 R37 R38 R39 R40 R41 R42 SW1 SW2 SW3 U3 U4 U5 U6
component class BlueNRG-LP: C1 C2 C3 C4 C5 C6 C7 C8 C9 C10 C11 C12 C13 C14 C15 C16 C30 C42 C43 C44 CN1 CN2 CN3 CN4 D1 J1 JP1 JP3 JP4 JP5 L1 L2 L3 L4 L5 L6 Q1 Q2 R1 R2 R3 R4 R5 R6 R7 R8 R9 R13 R17 R18 R20 R22 R24 R25

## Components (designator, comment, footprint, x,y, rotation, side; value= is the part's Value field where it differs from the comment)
BATT1 "Battery holder" PACCO_BATT_2 13.589,38.913 r270 bottom locked
BATT2 "CR2032" CR2032_BATTERY_HOLDER 29.453,1.041 r180 bottom
C1 "22p_0402" 0402_CAP_NP 63.781,34.526 r270 top
C2 "22p_0402" 0402_CAP_NP 62.273,34.51 r270 top
C3 "4u7_0402" 0402_CAP_NP 60.336,30.672 r270 top
C4 "100n_0402" 0402_CAP_NP 61.334,30.669 r270 top
C5 "0.4p_0402" 0402_CAP_NP 68.461,24.958 r90 top
C6 "0.1p_0402" 0402_CAP_NP 71.496,24.957 r90 top
C7 "220n_0402" 0402_CAP_NP 56.7,24.617 r0 top
C8 "4u7_0402" 0402_CAP_NP 56.806,27.02 r0 top
C9 "100n_0402" 0402_CAP_NP 56.799,26.037 r0 top
C10 "100n_0402" 0402_CAP_NP 67.416,28.027 r180 top
C11 "3p_0402" 0402_CAP_NP 67.419,27.029 r180 top
C12 "0.1p_0402" 0402_CAP_NP 74.223,24.965 r90 top
C13 "100n_0402" 0402_CAP_NP 57.308,22.714 r0 top
C14 "100n_0402" 0402_CAP_NP 67.238,23.281 r180 top
C15 "3p_0402" 0402_CAP_NP 67.234,22.32 r180 top
C16 "3.4p_0402" 0402_CAP_NP 69.985,25.868 r180 top
C17 "1u_0402" 0402_CAP_NP 14.072,20.168 r90 top
C19 "1u_0402" 0402_CAP_NP 20.422,20.168 r90 top
C20 "10n_0402" 0402_CAP_NP 10.414,44.348 r90 top
C21 "4.7u_0603" 0603_CAP_NP 37.046,41.123 r180 top
C22 "100n_0402" 0402_CAP_NP 34.569,39.065 r270 top
C23 "100n_0402" 0402_CAP_NP 36.779,39.726 r180 top
C24 "100n_0402" 0402_CAP_NP 39.116,37.948 r270 top
C25 "100n_0402" 0402_CAP_NP 50.785,38.989 r180 top
C26 "100n_0402" 0402_CAP_NP 46.046,36.959 r0 top
C27 "20p_0402" 0402_CAP_NP 3.116,21.26 r180 top
C28 "20p_0402" 0402_CAP_NP 2.972,33.706 r180 top
C29 "100n_0402" 0402_CAP_NP 6.901,17.272 r0 top
C30 "3.4p_0402" 0402_CAP_NP 66.856,25.471 r180 top
C31 "100n_0402" 0402_CAP_NP 16.434,29.312 r180 top
C32 "100n_0402" 0402_CAP_NP 14.199,24.028 r180 top
C33 "100n_0402" 0402_CAP_NP 7.163,31.648 r270 top
C34 "1u_0402" 0402_CAP_NP 8.23,31.648 r270 top
C35 "100n_0402" 0402_CAP_NP 8.306,23.571 r90 top
C36 "1u_0402" 0402_CAP_NP 7.239,23.571 r90 top
C39 "100n_0402" 0402_CAP_NP 11.252,31.496 r180 top
C40 "10n_0402" 0402_CAP_NP 14.351,13.352 r270 top
C41 "10n_0402" 0402_CAP_NP 23.546,13.581 r270 top
C42 "TBD" 0402_CAP_NP 75.489,25.002 r90 top
C43 "0.8p_0402" 0402_CAP_NP 78.816,25.002 r90 top
C44 "100p_0402" 0402_CAP_NP 75.489,27.28 r90 top
CN1 "CON10" HDR1X10 46.863,51.171 r180 top locked
CN2 "CON8" HDR1X8 33.126,2.916 r0 top locked
CN3 "CON8" HDR1X8 68.693,51.171 r180 top locked
CN4 "CON6" HDR1X6 56.004,2.916 r0 top
CN6 "USB micro B" "MICRO USB" 1.414,13.47 r90 top
CN7 "CONN" AMPMODE10_50M 2.388,43.307 r270 top
D1 "DEV3L" DEV3L0603 59.253,29.126 r90 top
D2 "DEV3L" DEV3L0603 29.743,29.515 r270 top
D3 "DEV3L" DEV3L0603 29.773,26.267 r270 top
Designator9 "Comment" FIDUCIAL 6.943,47.23 r0 top
Designator10 "Comment" FIDUCIAL 72.489,8.467 r0 top
DL1 "Diodo_led" "SMD _LED" 7.747,20.32 r0 top
DL2 "Diodo_led" "SMD _LED" 26.01,29.515 r180 top
DL3 "BLUE" "SMD _LED" 25.787,25.996 r180 top
DL4 "RED" "SMD _LED" 16.739,31.445 r180 top
J1 "UFL" UFL_SMT 73.339,30.385 r0 top value=SMA_RF
JP1 "Jumper 2" "HDR 2 X 1 M" 53.213,8.357 r90 top
JP2 "Jumper 3" "HDR 3 X 1 M" 27.203,19.355 r180 top
JP3 "Jumper 2" "HDR 2 X 1 M" 49.962,8.407 r90 top
JP4 "Jumper 2" "HDR 2 X 1 M" 46.812,8.382 r90 top
JP5 "Jumper 2" "HDR 2 X 1 M" 43.612,8.407 r90 top
L1 "2.4n_0402" 0402-A 69.996,25.011 r0 top
L2 "1n_0402" 0402-A 47.505,24.893 r0 top
L3 "2.7n_0402" 0402-A 77.249,25.502 r0 top
L4 "10n_0402" 0402-A 59.377,28.291 r180 top
L5 "2.4n_0402" 0402-A 72.96,25.457 r0 top
L6 "4.7u_0603" 0603_CAP_NP 47.401,21.866 r0 top
Q1 "XTAL_LS" NX2012SA 62.277,32.731 r0 top
Q2 "XTAL_HS" NX2016SA 64.804,31.074 r270 top
R1 "0_0402" 0402_RESISTOR 24.003,44.133 r90 top
R2 "0_0402" 0402_RESISTOR 26.581,44.133 r90 top
R3 "0_0402" 0402_RESISTOR 29.083,44.133 r90 top
R4 "0_0402" 0402_RESISTOR 34.163,44.133 r90 top
R5 "0_0402" 0402_RESISTOR 35.636,9.779 r90 top
R6 "0_0402" 0402_RESISTOR 36.703,44.133 r90 top
R7 "0_0402" 0402_RESISTOR 39.243,44.133 r90 top
R8 "0_0402" 0402_RESISTOR 33.139,9.786 r90 top
R9 "0_0402" 0402_RESISTOR 38.202,9.703 r90 top
R13 "0_0402" 0402_RESISTOR 55.994,44.107 r90 top
R17 "0_0402" 0402_RESISTOR 58.534,9.042 r90 top
R18 "0_0402" 0402_RESISTOR 61.074,44.107 r90 top
R20 "0_0402" 0402_RESISTOR 63.627,44.133 r90 top
R22 "0_0402" 0402_RESISTOR 66.142,44.12 r90 top
R24 "0_0402" 0402_RESISTOR 68.694,44.12 r90 top
R25 "0_0402" 0402_RESISTOR 68.72,9.042 r90 top
R26 "100k_0402" 0402_RESISTOR 9.195,44.196 r90 top
R27 "100_0402" 0402_RESISTOR 16.739,13.462 r270 top
R28 "100_0402" 0402_RESISTOR 20.244,45.491 r90 top
R29 "470_0402" 0402_RESISTOR 11.201,20.345 r0 top
R30 "100_0402" 0402_RESISTOR 24.765,13.691 r270 top
R31 "100k_0402" 0402_RESISTOR 15.57,13.462 r90 top
R32 "100k_0402" 0402_RESISTOR 22.327,13.716 r90 top
R33 "0_0402" 0402_RESISTOR 34.569,36.678 r90 top
R34 "10K_0402" 0402_RESISTOR 33.35,37.795 r270 top
R35 "0_0402" 0402_RESISTOR 37.389,34.011 r180 top
R36 "10K_0402" 0402_RESISTOR 37.338,35.331 r180 top
R37 "0_0402" 0402_RESISTOR 45.685,41.876 r180 top
R38 "0_0402" 0402_RESISTOR 47.596,43.053 r0 top
R39 "0_0402" 0402_RESISTOR 48.256,41.846 r0 top
R40 "680_0402" 0402_RESISTOR 30.429,31.547 r0 top
R41 "0_0402" 0402_RESISTOR 43.867,40.55 r0 top
R42 "0_0402" 0402_RESISTOR 43.875,39.038 r0 top
R43 "1.5k_0402" 0402_RESISTOR 7.493,12.04 r180 top
R44 "1M_0402" 0402_RESISTOR 7.239,27.356 r270 top
R45 "0_0402" 0402_RESISTOR 11.379,13.945 r180 top
R46 "0_0402" 0402_RESISTOR 11.379,15.85 r180 top
R47 "0_0402" 0402_RESISTOR 34.62,22.555 r180 top
R48 "0_0402" 0402_RESISTOR 34.62,23.825 r180 top
R49 "0_0402" 0402_RESISTOR 34.62,25.07 r0 top
R52 "5k_0402" 0402_RESISTOR 9.5,22.832 r90 top
R53 "0_0402" 0402_RESISTOR 34.62,21.26 r0 top
R54 "0_0402" 0402_RESISTOR 34.62,20.015 r180 top
R55 "100_0402" 0402_RESISTOR 16.459,28.143 r180 top
R56 "0_0402" 0402_RESISTOR 34.62,18.745 r180 top
R57 "1k_0402" 0402_RESISTOR 10.516,22.835 r270 top
R58 "1k5_0402" 0402_RESISTOR 6.833,37.592 r90 top
R59 "0_0402" 0402_RESISTOR 34.62,26.365 r180 top
R60 "0_0402" 0402_RESISTOR 16.434,26.797 r180 top
R61 "680_0402" 0402_RESISTOR 20.295,31.445 r0 top
ST1 "stlogo" stlogo 112.776,-39.516 r0 top
ST2 "EUlogo" EU_ROHS_1_2 36.779,29.87 r0 top
ST3 "RHoSlogo" CH_ROHS_2 61.976,39.675 r0 top
SW1 "RESET" B3FS_SWITCH 15.113,48.87 r90 top
SW2 "SW1" B3FS_SWITCH 14.757,5.105 r270 top
SW3 "SW2" B3FS_SWITCH 24.003,5.131 r270 top
TP1 "GND" TESTP 69.113,44.602 r270 top
TP2 "GND" TESTP 6.579,48.133 r270 top
TP3 "GND" TESTP 31.354,14.45 r270 top
U3 "LDLN025M33R" *SOT95P280X145-5N 17.145,19.863 r0 top
U4 "LPS22HB" HLGA-10L-2X2 35.903,38.24 r0 top
U5 "AAAF3529" AAAF3529L 25.06,33.225 r0 top
U6 "LSM6DS3" LGA14 45.721,40.468 r0 top
U7 "Part Number: STM32F10XRXY" PCBCOMPONENT_1 11.393,27.537 r0 top value=Value
U8 "USBLC6-2SC6" SOT23-6L_S 8.153,14.884 r90 top
V1 "VITE" "FORO 3MM" 75.248,4.013 r0 top
V2 "VITE" "FORO 3MM" 4.216,3.556 r0 top
V3 "VITE" "FORO 3MM" 76.098,50.114 r0 top
V4 "VITE" "FORO 3MM" 3.988,50.419 r0 top
X1 "8MHz" QUARZO 3.607,29.769 r270 top

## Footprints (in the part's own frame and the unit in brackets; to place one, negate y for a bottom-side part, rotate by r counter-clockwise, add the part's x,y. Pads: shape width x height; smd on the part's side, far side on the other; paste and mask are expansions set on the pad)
0402-A [mm] "Chip Inductor, Body 1.0x0.5mm, IPC High Density"
  rect 0.6x0.5 smd: 1(-0.5,0) 2(0.5,0)
  silkscreen extent -1.1,-0.15 -1.1,0.15, body extent -0.55,-0.3 0.55,0.3, height 0.55
0402_CAP_NP [mm]
  rect 0.635x0.508 smd mask+0: 1(-0.5,0) 2(0.5,0)
  silkscreen extent -0.97,-0.38 0.99,0.41, body extent -0.99,-0.36 1.04,0.36, height 0.82
0402_RESISTOR [mm]
  rect 0.635x0.508 smd mask+0: 1(-0.5,0) 2(0.5,0)
  silkscreen extent -0.97,-0.38 0.99,0.41, body extent -0.99,-0.36 1.04,0.36, height 0.82
0603_CAP_NP [mm]
  rect 0.8x1 smd: 1(-0.902,0) 2(0.902,0)
  silkscreen extent -1.41,-0.61 1.41,0.61, body extent -1.28,-0.46 1.26,0.48, height 0.82
*SOT95P280X145-5N [mm]
  rect 1.32x0.59 smd: 1(-1.145,0.95) 2(-1.145,0) 3(-1.145,-0.95) 4(1.145,-0.95) 5(1.145,0.95)
  silkscreen extent -2.5,-1.56 0.8,1.56, body extent -1.8,-1.24 1.8,1.24, height 0.51
AAAF3529L [mm]
  rect 1.15x0.699 smd: 1(0.01,0.01) 2(0.01,-0.84) 3(0.01,-1.69) 4(2.73,-1.69) 5(2.73,-0.84) 6(2.73,0.01)
  silkscreen extent 0.02,-2.06 2.75,0.38, body extent -0.57,-2.07 3.3,0.39, height 0.25
AMPMODE10_50M [mil]
  rect 35x35 hole 20: 1(0,0)
  round 35 hole 20: 2(0,50) 3(50,0) 4(50,50) 5(100,0) 6(100,50) 7(150,0) 8(150,50) 9(200,0) 10(200,50)
  silkscreen extent -117,-77 321,120
B3FS_SWITCH [mm]
  rect 1.6x1.4 smd: 1(3.998,-2.244) 2(-4.012,-2.244) 3(3.998,2.246) 4(-4.012,2.246)
  silkscreen extent -3.17,-3.15 3.14,3.16, body extent -4.57,-3.15 4.57,3.16, height 4.57
CH_ROHS_2 [mm]
  silkscreen extent -2.21,-1.75 1.96,1.85
CR2032_BATTERY_HOLDER [mil]
  rect 109.83x200 smd: 1(-55.52,276) 2(812.3,276)
  round 393.7 smd: 3(379.57,278)
  silkscreen extent -35,-33 794,567
DEV3L0603 [mil]
  rect 32x38 smd: 1(56,0) 2(0,0) 3(56,59)
  silkscreen extent -18,-21 74,80
EU_ROHS_1_2 [mm]
  silkscreen extent -3.17,-1.88 3.43,2.92
FIDUCIAL [mm]
  round 1 smd: 1(0,0)
"FORO 3MM" [mil]
  round 145 hole 125: 1(0,0)
  silkscreen extent -125,-125 125,125
HDR1X6 [mm] "Connector; Header; 6 Position"
  rect 1.5x1.5 hole 0.9 paste+0 mask+0: 1(0,0)
  round 1.5 hole 0.9 paste+0 mask+0: 2(2.54,0) 3(5.08,0) 4(7.62,0) 5(10.16,0) 6(12.7,0)
  silkscreen extent -1.27,-1.27 13.97,1.27, body extent -1.27,-1.27 13.97,1.27, height 8.5
HDR1X8 [mm] "Connector; Header; 8 Position"
  rect 1.5x1.5 hole 0.9 paste+0 mask+0: 1(0,0)
  round 1.5 hole 0.9 paste+0 mask+0: 2(2.54,0) 3(5.08,0) 4(7.62,0) 5(10.16,0) 6(12.7,0) 7(15.24,0) 8(17.78,0)
  silkscreen extent -1.27,-1.27 19.05,1.27, body extent -1.27,-1.27 19.05,1.27, height 8.5
HDR1X10 [mm] "Connector; Header; 10 Position"
  rect 1.5x1.5 hole 0.9 paste+0 mask+0: 1(0,0)
  round 1.5 hole 0.9 paste+0 mask+0: 2(2.54,0) 3(5.08,0) 4(7.62,0) 5(10.16,0) 6(12.7,0) 7(15.24,0) 8(17.78,0) 9(20.32,0) 10(22.86,0)
  silkscreen extent -1.27,-1.27 24.13,1.27, body extent -1.27,-1.27 24.13,3.93, height 8.5
"HDR 2 X 1 M" [mm] "Connector; Header; 2 Position"
  rect 1.5x1.5 hole 0.9: 1(-1.27,0)
  round 1.5 hole 0.9: 2(1.27,0)
  silkscreen extent -2.54,-1.27 2.54,1.27, body extent -2.54,-1.27 2.54,1.27, height 8.38
"HDR 3 X 1 M" [mm] "Connector; Header; 3 Position"
  rect 1.5x1.5 hole 0.9: 1(-2.54,0)
  round 1.5 hole 0.9: 2(0,0) 3(2.54,0)
  silkscreen extent -3.81,-1.27 3.81,1.27, body extent -3.81,-1.24 3.81,1.24, height 8.54
HLGA-10L-2X2 [mil]
  rect 25x11.8 smd: 1(-2,-15) 2(-2,-37) 6(65.5,-37) 7(65.5,-15.5)
  rect 11.8x25 smd: 3(10,-59.5) 4(31.5,-59.5) 5(53,-59.5) 8(52.5,7.5) 9(31.5,8) 10(9.5,8)
  silkscreen extent -8,-66 71,14, body extent -14,-72 78,20, height 20
LGA14 [mil]
  rect 25x9.83 smd: 1(-1,3) 2(-1,-17) 3(-1,-37) 4(-1,-57) 8(103,-57) 9(103,-37) 10(103,-17) 11(103,3)
  rect 9.83x25 smd: 5(31,-71) 6(51,-71) 7(71,-71) 12(71,16) 13(51,16) 14(31,16)
  silkscreen extent -8,-77 110,23, body extent -14,-84 116,28, height 20
"MICRO USB" [mm]
  rect 0.4x1.35 smd: 1(2.45,-2.675) 2(1.8,-2.675) 3(1.15,-2.675) 4(0.5,-2.675) 5(-0.15,-2.675)
  rect 1.6x1.4 smd: 6(-2.05,-2.45) 11(4.35,-2.45)
  rect 2.3x1.3 smd: 7(-2.6,0) 10(4.9,0)
  rect 1.8x1.9 smd: 8(0,0) 9(2.3,0)
  silkscreen extent -4.12,-3.67 6.44,1.3, body extent -3.26,-2.9 5.54,2.7, height 2.53
NX2012SA [mil]
  rect 40x50 smd: 1(0,0) 2(60,0)
  silkscreen extent -21,-26 81,26, body extent -20,-25 80,25, height 20
NX2016SA [mm]
  rect 0.599x0.799 smd: 1(0,0) 2(1.8,0) 3(1.8,1.2) 4(0,1.2)
  silkscreen extent -0.35,-0.45 2.15,1.65, body extent -0.3,-0.4 2.1,1.6, height 0.51
PACCO_BATT_2 [mil]
  rect 100x100 hole 43: 1(172,0) 2(0,0)
  silkscreen extent -409,-2284 580,76
PCBCOMPONENT_1 [mil]
  round 12 smd paste+0 mask+0: A1(68.95,-68.95) A2(49.25,-68.95) A3(29.55,-68.95) A4(9.85,-68.95) A5(-9.85,-68.95) A6(-29.55,-68.95) A7(-49.25,-68.95) A8(-68.95,-68.95) B1(68.95,-49.25) B2(49.25,-49.25) B3(29.55,-49.25) B4(9.85,-49.25) B5(-9.85,-49.25) B6(-29.55,-49.25) B7(-49.25,-49.25) B8(-68.95,-49.25) C1(68.95,-29.55) C2(49.25,-29.55) C3(29.55,-29.55) C4(9.85,-29.55) C5(-9.85,-29.55) C6(-29.55,-29.55) C7(-49.25,-29.55) C8(-68.95,-29.55) D1(68.95,-9.85) D2(49.25,-9.85) D3(29.55,-9.85) D4(9.85,-9.85) D5(-9.85,-9.85) D6(-29.55,-9.85) D7(-49.25,-9.85) D8(-68.95,-9.85) E1(68.95,9.85) E2(49.25,9.85) E3(29.55,9.85) E4(9.85,9.85) E5(-9.85,9.85) E6(-29.55,9.85) E7(-49.25,9.85) E8(-68.95,9.85) F1(68.95,29.55) F2(49.25,29.55) F3(29.55,29.55) F4(9.85,29.55) F5(-9.85,29.55) F6(-29.55,29.55) F7(-49.25,29.55) F8(-68.95,29.55) G1(68.95,49.25) G2(49.25,49.25) G3(29.55,49.25) G4(9.85,49.25) G5(-9.85,49.25) G6(-29.55,49.25) G7(-49.25,49.25) G8(-68.95,49.25) H1(68.95,68.95) H2(49.25,68.95) H3(29.55,68.95) H4(9.85,68.95) H5(-9.85,68.95) H6(-29.55,68.95) H7(-49.25,68.95) H8(-68.95,68.95)
  silkscreen extent -98,-97 98,97, body extent -75,-75 75,75, height 20
QUARZO [mil]
  round 60 hole 32: 1(0,0) 2(200,0)
  silkscreen extent -99,-94 299,94, body extent -103,-98 303,98, height 80
"SMD _LED" [mm]
  rect 1.3x1.6 smd: 1(0.948,0.006) 2(-0.952,0.006)
  silkscreen extent -2.13,-1.14 2,1.16, body extent -1.52,-0.64 1.52,0.64, height 1.27
SOT23-6L_S [mil]
  rect 23.6x47.23 smd: 1(-37,-42.12) 2(0,-42.12) 3(37.8,-42.12) 4(36.22,51.18) 5(0,51.17) 6(-37,51.17)
  silkscreen extent -78,-55 55,22, body extent -49,-66 50,75, height 20
stlogo [mm]
  silkscreen extent -44.96,50.81 -33.53,56.9
TESTP [mil]
  round 66 hole 50: 1(-50,100)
